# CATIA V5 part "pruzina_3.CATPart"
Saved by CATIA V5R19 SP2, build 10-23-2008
Part number: Pruzina delka 20mm
Bounding box of the stored display mesh (mm): x -8 to 8, y -8 to 8, z 0 to 20
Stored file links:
  D:\DURATEC\pruzina_3.CATPart
  D:\DURATEC\pruzina_1.CATPart
  D:\DURATEC\Pohyb pruziny.CATProduct
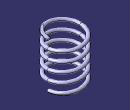
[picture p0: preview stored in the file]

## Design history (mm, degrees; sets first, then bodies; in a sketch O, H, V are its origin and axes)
External parameters (linked from other documents)
  `External.Delka pruziny` = 20 mm
  `External.Pocet zavitu` = 5
  `External.Vnitrni prumer pruziny` = 13 mm
  `External.Prumer dratu` = 1.5 mm
Set1
  Plane1: type Normal, Curve {line type PtDir, Direction (0, 0, 1), Start 0, End 20 {= `External.Delka pruziny`}, RefPoint {point type Coord, X 0, Y 0, Z 0}}, RefPoint vertex of Plane1
  Sketch1 on zx-plane, origin (0, 0, 0), H (-1, 0, 0), V (0, 0, 1)
    line L1 (6.5, 19) -> (6.5, 14)
    construction line L2 (6.5, 14) -> (-6.5, 14)
    line L3 (-6.5, 14) -> (-6.5, 19)
    construction line L4 (-6.5, 19) -> (6.5, 19)
    reference intersected line E1 through (0, 20) direction (-1, 0) from Plane1
    distance L3 L1 = 13 {= `External.Vnitrni prumer pruziny`}
    length L1 = 5
    distance L4 E1 = 1
    vertical: L1 V, L3 V
    horizontal: L2 H, L4 H
    equidistance: L1 L3 O
  Line1: type PtDir, Direction (0, 0, 1), Start 0, End 20 {= `External.Delka pruziny`}, RefPoint {point type Coord, X 0, Y 0, Z 0}
Body1 "Pruzina" (main body)
  Helix1: Pitch 4 {= `External.Delka pruziny` /`External.Pocet zavitu`}, TaperAngle 0, Height 20 {= Plane1.End}, Direction {line type PtDir, Direction (0, 0, 1), Start 0, End 20 {= `External.Delka pruziny`}, RefPoint {point type Coord, X 0, Y 0, Z 0}}, RefPoint {point type Coord, X 7.25 {= `External.Vnitrni prumer pruziny` /2+`External.Prumer dratu` /2}, Y 0, Z 0}
  Sketch2 on zx-plane, origin (0, 0, 0), H (-1, 0, 0), V (0, 0, 1)
    circle A1 centre (-7.25, 0) radius 0.75
    point P1 (-7.25, 0)
    reference projected point E1 (-7.25, 0) from vertex of Helix1
    radius A1 = 0.75 {= `External.Prumer dratu` /2}
    distance V A1 = 6.5 (reference)
    distance V A1 = 8 (reference)
    coincidence: P1 E1
  Rib1: profile Sketch2, centre curve Helix1
  Split1: SplitPlane xy-plane
  Split2: SplitPlane Plane1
